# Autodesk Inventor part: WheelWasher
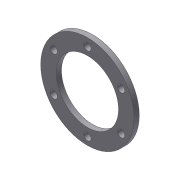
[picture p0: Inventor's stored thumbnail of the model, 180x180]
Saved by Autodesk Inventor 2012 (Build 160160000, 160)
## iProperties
Created: 2013-01
Part Number: WheelWasher
Material: Aluminum-6061
Document SubType Name: Modeling
Designer: Owner
Density: 2.71 g/cm^3
Mass: 11.4425 g
Surface Area: 38.7887 cm^2
Volume: 4.22233 cm^3
Author: Owner
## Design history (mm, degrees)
sketch "Sketch1"
  geometry: C1 r 28.575 at (0, 0); C2 r 19.05 at (0, 0); 1 further point
  constraints: 2 centre point, 2 coincident
  dimensions: "d0" = 38.1 diameter of C2; "d1" = 57.15 diameter of C1
extrude "Extrusion1" new body sketch "Sketch1" distance "d2" = 3.175; taper "d3" = 0 deg
sketch "Sketch2" dims "d4" = 47.625
  geometry: L1 (0, 23.812)-(0, 0); L2 (-20.622, 11.906)-(0, 0); L3 (-20.622, -11.906)-(0, 0); L4 (0, -23.812)-(0, 0); L5 (20.622, -11.906)-(0, 0); L6 (20.622, 11.906)-(0, 0); C1 r 19.05 at (0, 0) reference; C2 r 28.575 at (0, 0) reference; 6 further points
  constraints: 12 end point, 7 coincident, 1 vertical, 1 vertical alignment, 21 other
  dimensions: "d7" = 360 deg dimension on C1.centre L1.start (derived)
hole "Hole1" sketch "Sketch2" at (0, 23.812), (20.622, 11.906), (20.622, -11.906), (0, -23.812), (-20.622, -11.906), (-20.622, 11.906) diameter "d9" = 4.4958; stored, may be unused: countersink angle "d13" = 82 deg, drill point angle "d15" = 118 deg; dims "d10" = 19.05, "d11" = 8.4328, "d12" = 6.35, "d14" = 25.4
body "Solid1"
